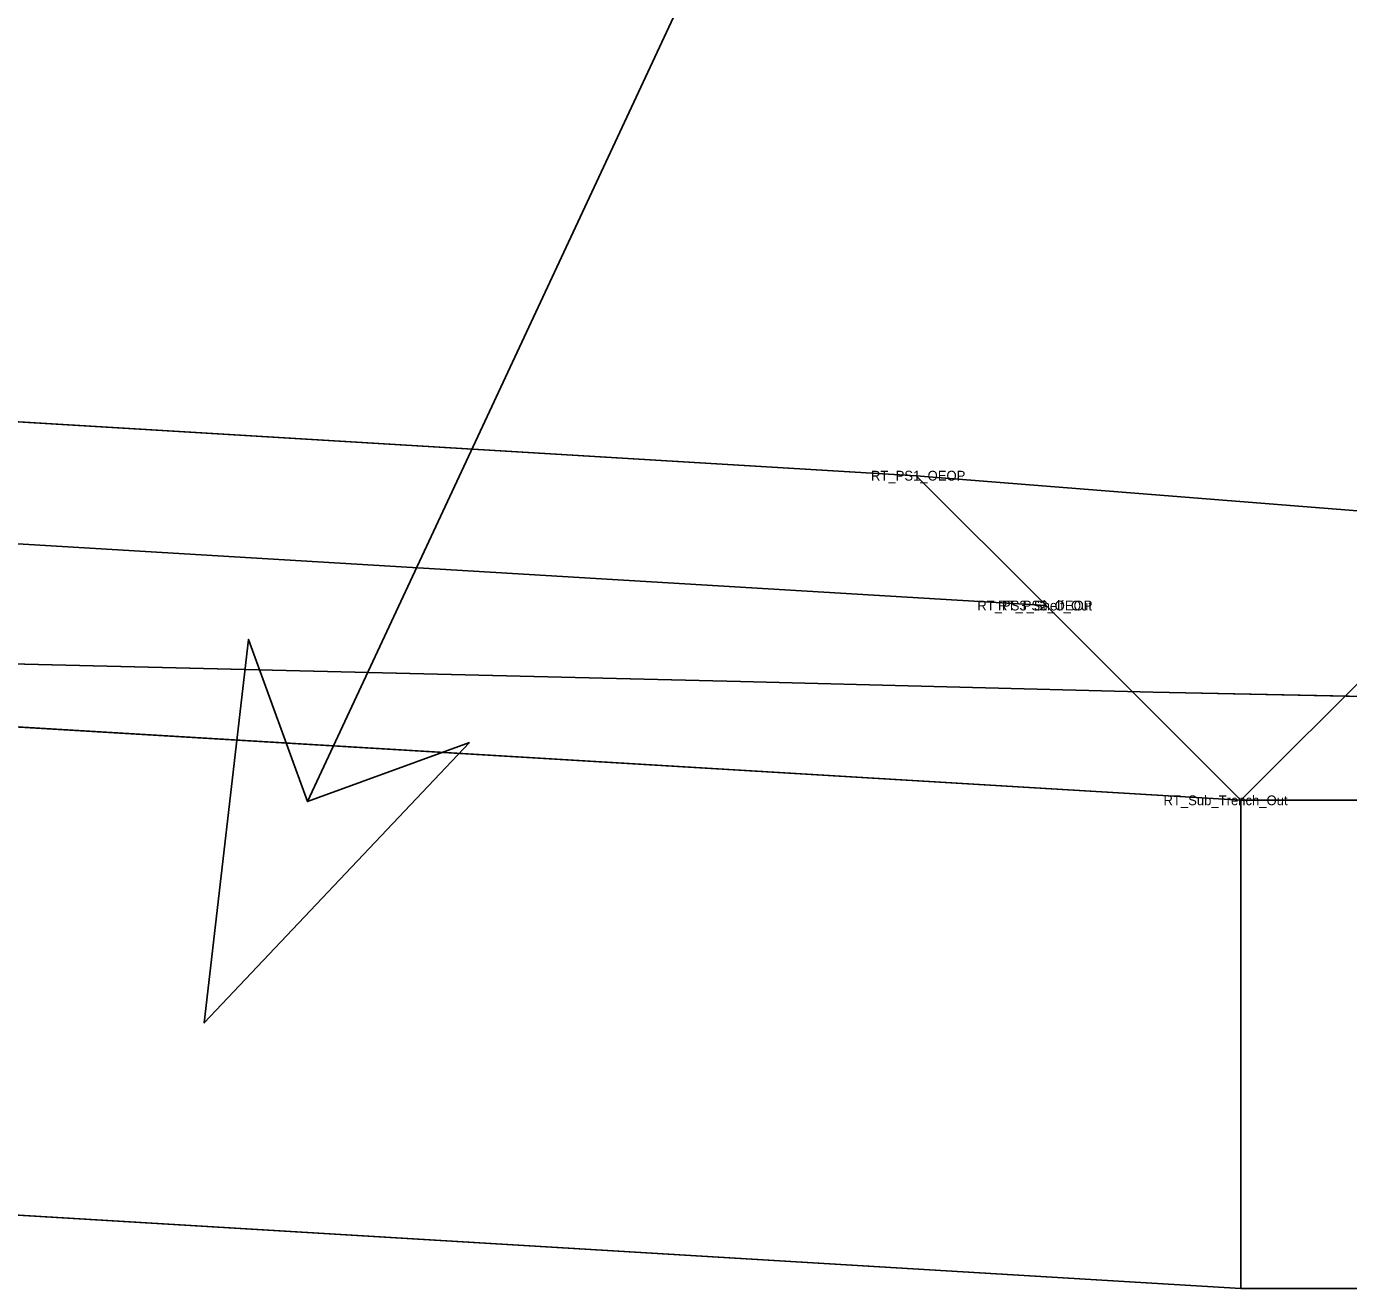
# Model space of a CAD drawing. Extents: x -516 to 303, y -10 to 5017.
# Drawn here: x 162.178 to 164.886, y 2504.204 to 2506.79 of the extents above; entities that cross this region are included whole.
import ezdxf

# ---------------------------------------------------------------- set-up
doc = ezdxf.new("R2010")
doc.units = 0
for name, color, linetype in [('Exist XS Ground Line', 7, 'Continuous'), ('Prop CMT Pvmt Surface Shoulder', 7, 'Continuous'), ('Prop CMT Shld Paved Course 1', 7, 'Continuous'), ('Prop CMT Shld Paved Course 2', 7, 'Continuous'), ('Prop CMT Shld Paved Course 3', 7, 'Continuous'), ('Prop CMT Slope Grass', 7, 'Continuous'), ('Prop CMT Subgrade Earthwork', 7, 'Continuous'), ('Prop Road Sect_ Misc - Drafting Aid (solid line)', 7, 'Continuous'), ('Prop Road Sect_ Misc - Drafting Aid (Tx - small)', 7, 'Continuous'), ('Prop Road Sect_ Recs - UC Shallow (Outline)', 7, 'Continuous'), ('Prop Road Sect_ Recs - UC Shallow (Pattern)', 7, 'Continuous'), ('Scratch_Level_0', 7, 'Continuous')]:
    doc.layers.add(name, color=color, linetype=linetype)

msp = doc.modelspace()

# ---------------------------------------------------------------- linework, layer by layer
at = {"layer": 'Exist XS Ground Line'}
msp.add_lwpolyline([(131.6756, 2506.039), (149.0951, 2505.7181), (150.1702, 2505.6981), (151.2449, 2505.6798), (153.9281, 2505.658), (155.8468, 2505.6298), (156.5413, 2505.6134), (157.7961, 2505.5833), (159.1952, 2505.5519), (159.7504, 2505.5399), (161.3095, 2505.5036), (161.8359, 2505.4913), (163.6405, 2505.4476), (164.4857, 2505.426), (165.5232, 2505.4046), (166.0583, 2505.3912), (166.8223, 2505.373), (167.2292, 2505.3687), (168.2607, 2505.3287)], dxfattribs=at)
at = {"layer": 'Prop CMT Pvmt Surface Shoulder'}
msp.add_line((162, 2505.9894), (164, 2505.8694), dxfattribs=at)
at = {"layer": 'Prop CMT Shld Paved Course 1'}
for points in [[(162, 2505.9894), (164, 2505.8694), (164.266, 2505.6034)], [(164.266, 2505.6034), (162, 2505.7394)]]:
    msp.add_lwpolyline(points, dxfattribs=at)
at = {"layer": 'Prop CMT Shld Paved Course 2'}
for points in [[(162, 2505.7394), (164.266, 2505.6034)], [(164.266, 2505.6034), (162, 2505.7394)], [(164.266, 2505.6034), (164.266, 2505.6034)]]:
    msp.add_lwpolyline(points, dxfattribs=at)
at = {"layer": 'Prop CMT Shld Paved Course 3'}
for points in [[(162, 2505.7394), (164.266, 2505.6034)], [(164.266, 2505.6034), (164.266, 2505.6034)], [(164.266, 2505.6034), (164.6649, 2505.2045)], [(164.6649, 2505.2045), (162, 2505.3644)]]:
    msp.add_lwpolyline(points, dxfattribs=at)
at = {"layer": 'Prop CMT Slope Grass'}
msp.add_line((164, 2505.8694), (170, 2505.3894), dxfattribs=at)
at = {"layer": 'Prop CMT Subgrade Earthwork'}
for p, q in [((164.6649, 2505.2045), (165.2313, 2505.7709)), ((162, 2505.3644), (164.6649, 2505.2045))]:
    msp.add_line(p, q, dxfattribs=at)
at = {"layer": 'Prop Road Sect_ Misc - Drafting Aid (solid line)'}
for p, q in [((164.6649, 2505.2045), (164.6649, 2504.2045)), ((164.6649, 2505.2045), (165.6649, 2505.2045)), ((162, 2504.3643), (164.6649, 2504.2045)), ((164.6649, 2504.2045), (165.6649, 2504.2045))]:
    msp.add_line(p, q, dxfattribs=at)
at = {"layer": 'Prop Road Sect_ Misc - Drafting Aid (Tx - small)'}
msp.add_line((164.7953, 2509.5796), (162.7536, 2505.2018), dxfattribs=at)
msp.add_lwpolyline([(163.0858, 2505.3227), (162.5423, 2504.7487), (162.6327, 2505.534), (162.7536, 2505.2018)], close=True, dxfattribs=at)
at = {"layer": 'Prop Road Sect_ Recs - UC Shallow (Outline)'}
msp.add_lwpolyline([(165.6649, 2504.2045), (165.6649, 2505.2045), (165.6649, 2505.401), (165.5232, 2505.4046), (164.4857, 2505.426), (163.6405, 2505.4476), (161.8359, 2505.4913), (159.7504, 2505.5399), (159.1952, 2505.5519), (157.7961, 2505.5833), (156.5413, 2505.6134), (155.8468, 2505.6298), (153.9281, 2505.658), (151.2449, 2505.6798), (150, 2505.7013), (149.0951, 2505.7181), (148.0015, 2505.7383), (148, 2505.5794), (162, 2504.3643), (164.6649, 2504.2045)], close=True, dxfattribs=at)
at = {"layer": 'Prop Road Sect_ Recs - UC Shallow (Pattern)'}
msp.add_lwpolyline([(165.6649, 2504.2045), (165.6649, 2505.2045), (165.6649, 2505.401), (165.5232, 2505.4046), (164.4857, 2505.426), (163.6405, 2505.4476), (161.8359, 2505.4913), (159.7504, 2505.5399), (159.1952, 2505.5519), (157.7961, 2505.5833), (156.5413, 2505.6134), (155.8468, 2505.6298), (153.9281, 2505.658), (151.2449, 2505.6798), (150, 2505.7013), (149.0951, 2505.7181), (148.0015, 2505.7383), (148, 2505.5794), (162, 2504.3643), (164.6649, 2504.2045), (165.6649, 2504.2045)], dxfattribs=at)

# ---------------------------------------------------------------- texts
at = {"layer": 'Scratch_Level_0'}
for s, p in [('RT_PS1_OEOP', (163.9076, 2505.8594)), ('RT_PS3_Shelf_Out', (164.1253, 2505.5934)), ('RT_PS3_OEOP', (164.1678, 2505.5934)), ('RT_PS2_OEOP', (164.1678, 2505.5934)), ('RT_Sub_Trench_Out', (164.5065, 2505.1945))]:
    msp.add_text(s, height=0.02, dxfattribs=at).set_placement(p)

doc.saveas('drawing.dxf')
